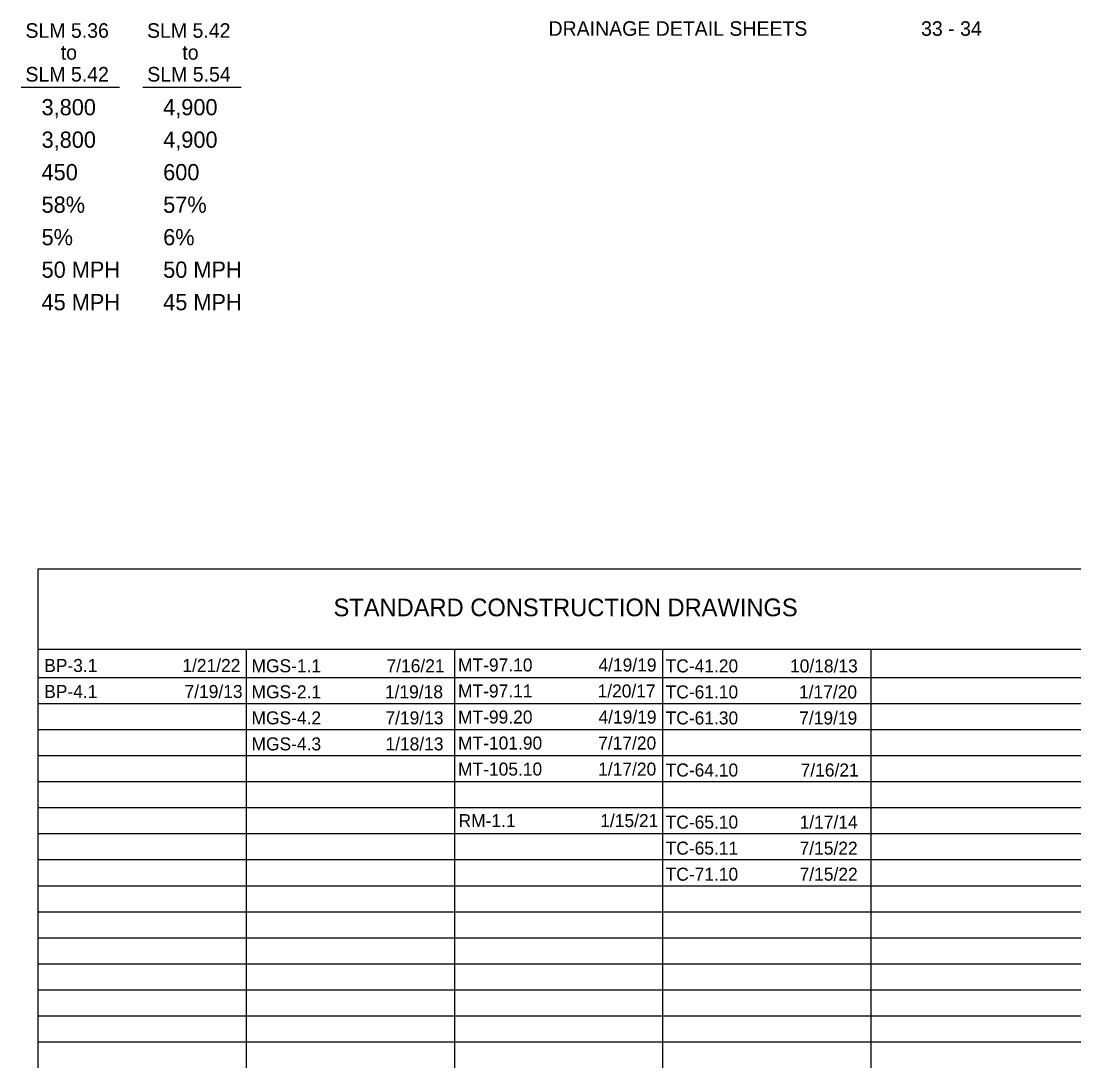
# Model space of a CAD drawing. Extents: x -59 to 82, y -3 to 49.
# Drawn here: x -47.01 to -36.9, y 28.89 to 38.94 of the extents above; entities that cross this region are included whole.
import ezdxf

# ---------------------------------------------------------------- set-up
doc = ezdxf.new("R2010")
doc.units = 0
doc.layers.add('SH_Data', color=7, linetype='Continuous')
doc.layers.add('SH_Text', color=7, linetype='Continuous')

msp = doc.modelspace()

# ---------------------------------------------------------------- linework, layer by layer
at = {"layer": 'SH_Data'}
for p, q in [((-46.848, 33.683), (-33.398, 33.683)), ((-46.848, 28.891), (-46.848, 33.683)), ((-46.848, 32.912), (-33.398, 32.912)), ((-44.848, 28.891), (-44.848, 32.912)), ((-42.848, 28.891), (-42.848, 32.912)), ((-40.848, 28.891), (-40.848, 32.912)), ((-38.848, 28.891), (-38.848, 32.912)), ((-46.848, 32.641), (-33.398, 32.641)), ((-46.848, 32.391), (-33.398, 32.391)), ((-46.848, 32.141), (-33.398, 32.141)), ((-46.848, 31.891), (-33.398, 31.891)), ((-46.848, 31.641), (-33.398, 31.641)), ((-46.848, 31.391), (-33.398, 31.391)), ((-46.848, 31.141), (-33.398, 31.141)), ((-46.848, 30.891), (-33.398, 30.891)), ((-46.848, 30.641), (-33.398, 30.641)), ((-46.848, 30.391), (-33.398, 30.391)), ((-46.848, 30.141), (-33.398, 30.141)), ((-46.848, 29.891), (-33.398, 29.891)), ((-46.848, 29.641), (-33.398, 29.641)), ((-46.848, 29.391), (-33.398, 29.391)), ((-46.848, 29.141), (-33.398, 29.141))]:
    msp.add_line(p, q, dxfattribs=at)
at = {"layer": 'SH_Text'}
for p, q in [((-47.013, 38.309), (-46.068, 38.309)), ((-45.845, 38.309), (-44.9, 38.309))]:
    msp.add_line(p, q, dxfattribs=at)

# ---------------------------------------------------------------- texts
at = {"layer": 'SH_Data'}
for s, p in [('3,800', (-46.816, 38.038)), ('4,900', (-45.648, 38.038)), ('3,800', (-46.816, 37.726)), ('4,900', (-45.648, 37.726)), ('450', (-46.816, 37.414)), ('600', (-45.648, 37.414)), ('58%', (-46.816, 37.102)), ('57%', (-45.648, 37.102)), ('5%', (-46.816, 36.79)), ('6%', (-45.648, 36.79)), ('50 MPH', (-46.816, 36.478)), ('50 MPH', (-45.648, 36.478)), ('45 MPH', (-46.816, 36.166)), ('45 MPH', (-45.648, 36.166))]:
    msp.add_text(s, height=0.156, dxfattribs=at).set_placement(p)
at = {"layer": 'SH_Text'}
for s, height, p in [('DRAINAGE DETAIL SHEETS                     33 - 34', 0.14, (-41.947, 38.801)), ('SLM 5.36', 0.14, (-46.971, 38.782)), ('SLM 5.42', 0.14, (-45.803, 38.782)), ('to', 0.14, (-46.632, 38.572)), ('to', 0.14, (-45.464, 38.572)), ('SLM 5.42', 0.14, (-46.971, 38.362)), ('SLM 5.54', 0.14, (-45.801, 38.362)), ('STANDARD CONSTRUCTION DRAWINGS', 0.17, (-44.012, 33.228)), ('BP-3.1', 0.125, (-46.791, 32.693)), ('1/21/22', 0.125, (-45.464, 32.693)), ('MGS-1.1', 0.125, (-44.8, 32.69)), ('7/16/21', 0.125, (-43.503, 32.69)), ('MT-97.10', 0.125, (-42.816, 32.698)), ('4/19/19', 0.125, (-41.467, 32.698)), ('TC-41.20', 0.125, (-40.822, 32.689)), ('10/18/13', 0.125, (-39.627, 32.689)), ('BP-4.1', 0.125, (-46.791, 32.443)), ('7/19/13', 0.125, (-45.443, 32.443)), ('MGS-2.1', 0.125, (-44.8, 32.44)), ('1/19/18', 0.125, (-43.518, 32.44)), ('MT-97.11', 0.125, (-42.816, 32.448)), ('1/20/17', 0.125, (-41.476, 32.448)), ('TC-61.10', 0.125, (-40.822, 32.439)), ('1/17/20', 0.125, (-39.541, 32.439)), ('MGS-4.2', 0.125, (-44.8, 32.19)), ('7/19/13', 0.125, (-43.513, 32.19)), ('MT-99.20', 0.125, (-42.816, 32.198)), ('4/19/19', 0.125, (-41.467, 32.198)), ('TC-61.30', 0.125, (-40.822, 32.189)), ('7/19/19', 0.125, (-39.539, 32.189)), ('MGS-4.3', 0.125, (-44.8, 31.94)), ('1/18/13', 0.125, (-43.513, 31.94)), ('MT-101.90', 0.125, (-42.816, 31.948)), ('7/17/20', 0.125, (-41.47, 31.948)), ('MT-105.10', 0.125, (-42.816, 31.698)), ('1/17/20', 0.125, (-41.47, 31.698)), ('TC-64.10', 0.125, (-40.822, 31.689)), ('7/16/21', 0.125, (-39.525, 31.689)), ('RM-1.1', 0.125, (-42.811, 31.203)), ('1/15/21', 0.125, (-41.45, 31.203)), ('TC-65.10', 0.125, (-40.822, 31.189)), ('1/17/14', 0.125, (-39.535, 31.189)), ('TC-65.11', 0.125, (-40.822, 30.939)), ('7/15/22', 0.125, (-39.535, 30.939)), ('TC-71.10', 0.125, (-40.822, 30.689)), ('7/15/22', 0.125, (-39.535, 30.689))]:
    msp.add_text(s, height=height, dxfattribs=at).set_placement(p)

doc.saveas('drawing.dxf')
